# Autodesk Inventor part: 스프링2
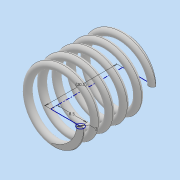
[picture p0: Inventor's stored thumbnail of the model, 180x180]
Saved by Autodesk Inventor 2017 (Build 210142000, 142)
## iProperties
Part Number: 스프링2
Material: 일반
Document SubType Name: Modeling
Designer: MRC
Density: 1 g/cm^3
Appearance: 기본값
Author: MRC
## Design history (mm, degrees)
sketch "스케치1"
  geometry: L1 (0, 0)-(0, 20.5); L2 (0, 0)-(8.5, 0); L3 (0, 20.5)-(8.5, 20.5); C1 r 1 at (8.5, 0)
  constraints: 6 end point, 2 horizontal, 1 centre point, 1 coincident, 1 vertical
  dimensions: "d0" = 20.5 distance of L1.start L1.end (derived); "d1" = 8.5 distance of L1.start L2.end; "d2" = 2 diameter of C1
feature "코일1" pitch "d3" = 10; turns "d5" = 5; dims "d4" = 20.5 (= d0), "d6" = 0, angle "d7" = 90 deg, angle "d8" = 90 deg, "d9" = 0, "d10" = 0
sketch "스케치2"
  geometry: L1 (20.5, 13.489)-(0, 13.489); L2 (0, 13.489)-(0, -13.489); L3 (0, -13.489)-(20.5, -13.489); L4 (20.5, -13.489)-(20.5, 13.489); 2 further points
  constraints: 8 end point, 2 parallel, 1 coincident, 1 horizontal, 1 midpoint, 1 perpendicular
  dimensions: "d11" = 20.5 distance of L2.end L3.end (= d0)
extrude "돌출1" sketch "스케치2" stored distance "d12" = 0; taper "d13" = 0 deg
node "솔리드1"
